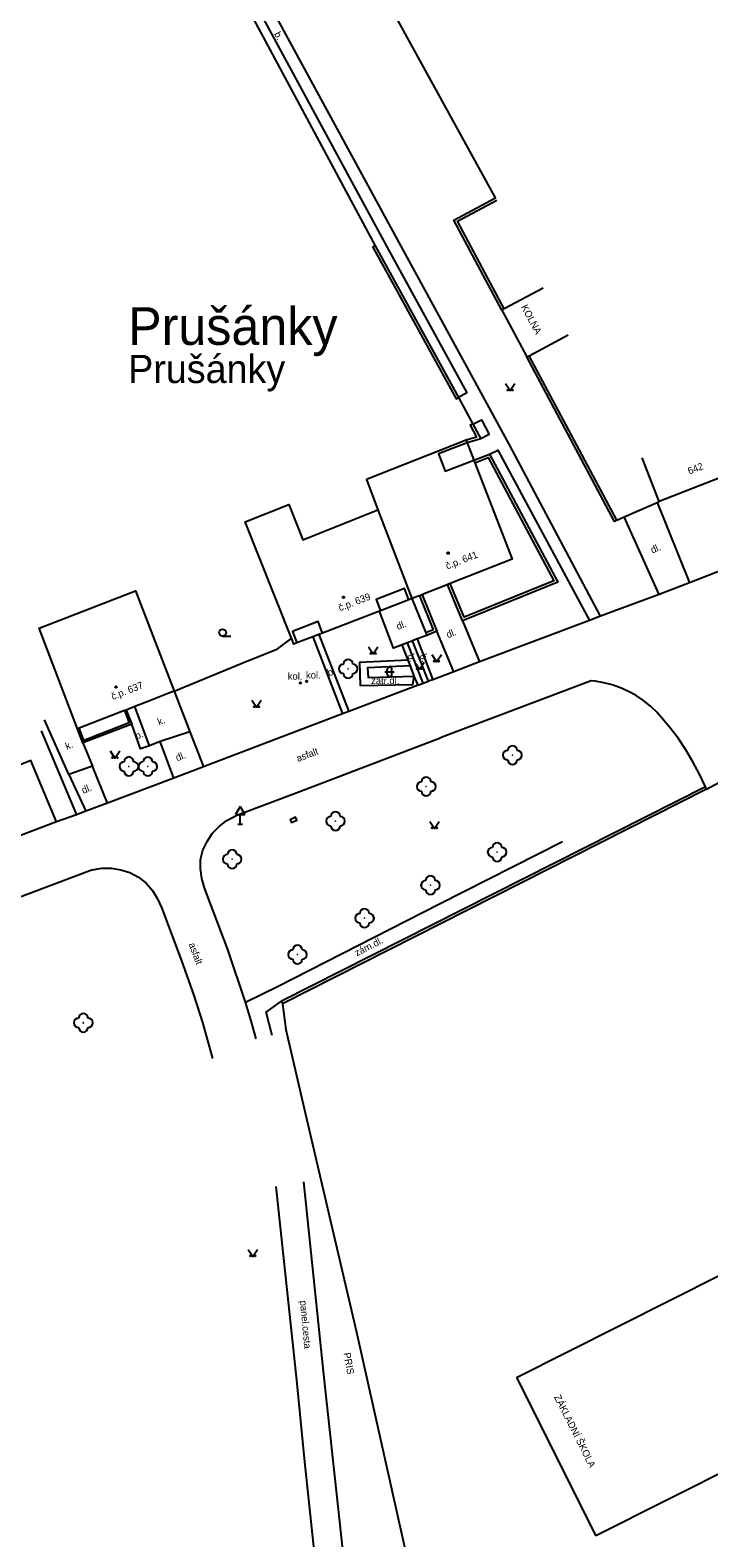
# Model space of a CAD drawing. Extents: x -577457 to -568404, y -1208466 to -1201387.
# Drawn here: x -574973.4 to -574901.1, y -1204276 to -1204115.5 of the extents above; entities that cross this region are included whole.
import ezdxf

# ---------------------------------------------------------------- set-up
doc = ezdxf.new("R2010")
doc.units = 0
for name, color, linetype in [('BUDOVY_MĚŘ', 7, 'Continuous'), ('BUDOVY_NEMĚŘ', 7, 'Continuous'), ('NÁZEV_K_Ú', 7, 'Continuous'), ('NÁZVY_SÍDEL_JEDNOTKY', 7, 'Continuous'), ('OBVOD_PILÍŘE', 7, 'Continuous'), ('POMOC_POPIS', 7, 'Continuous'), ('ROZHRANÍ_PLOCH', 7, 'Continuous'), ('ZELEŇ', 7, 'Continuous'), ('ZN_BP', 7, 'Continuous'), ('ZN_BUDOV', 7, 'Continuous'), ('ZN_DOPLŇKOVÉ', 7, 'Continuous'), ('ZN_KULTUR', 7, 'Continuous'), ('Č_POPIS_ORIENT', 7, 'Continuous')]:
    doc.layers.add(name, color=color, linetype=linetype)

msp = doc.modelspace()

# ---------------------------------------------------------------- linework, layer by layer
at = {"layer": 'BUDOVY_MĚŘ'}
for points in [[(-574918.74, -1204143), (-574922.89, -1204145.21)], [(-574922.89, -1204145.21), (-574923.15, -1204145.35)], [(-574923.15, -1204145.35), (-574920.5, -1204150.32)], [(-574920.23, -1204150.18), (-574916.09, -1204147.96)], [(-574920.5, -1204150.32), (-574920.23, -1204150.18)], [(-574926.96, -1204159.17), (-574926.85, -1204159.45)], [(-574926.85, -1204159.45), (-574926.14, -1204161.3)], [(-574926.03, -1204161.58), (-574922.06, -1204171.84), (-574928.65, -1204174.43)], [(-574926.14, -1204161.3), (-574926.03, -1204161.58)], [(-574906.38, -1204165.7), (-574908.2, -1204161.05)], [(-574897.04, -1204162.05), (-574906.38, -1204165.7)], [(-574928.93, -1204174.54), (-574928.98, -1204174.56)], [(-574928.65, -1204174.43), (-574928.93, -1204174.54)], [(-574933.04, -1204176.15), (-574933.5, -1204174.96), (-574936.52, -1204176.12), (-574936.06, -1204177.32)], [(-574933.04, -1204176.15), (-574936.06, -1204177.32)], [(-574932.72, -1204176.03), (-574933.04, -1204176.15)], [(-574931.91, -1204175.72), (-574932.72, -1204176.03)], [(-574931.64, -1204175.61), (-574931.91, -1204175.72)], [(-574931.58, -1204175.59), (-574931.64, -1204175.61)], [(-574936.17, -1204177.36), (-574942.23, -1204179.7)], [(-574936.06, -1204177.32), (-574936.17, -1204177.36)], [(-574942.23, -1204179.7), (-574942.69, -1204178.48), (-574945.45, -1204179.54), (-574944.99, -1204180.75)], [(-574944.99, -1204180.75), (-574945.29, -1204180.87), (-574945.54, -1204180.22)], [(-574943.29, -1204180.1), (-574944.99, -1204180.75)], [(-574942.63, -1204179.85), (-574943.29, -1204180.1)], [(-574942.23, -1204179.7), (-574942.63, -1204179.85)], [(-574960.91, -1204187.01), (-574962.22, -1204187.52)], [(-574958.04, -1204185.88), (-574958.6, -1204186.1)], [(-574963.34, -1204187.95), (-574968.15, -1204189.83)], [(-574963.15, -1204187.88), (-574963.34, -1204187.95)], [(-574968.15, -1204189.83), (-574968.34, -1204189.9)], [(-574921.6, -1204258.9), (-574913.15, -1204275.74)]]:
    msp.add_lwpolyline(points, dxfattribs=at)
at = {"layer": 'BUDOVY_NEMĚŘ'}
for points in [[(-574926.96, -1204159.17), (-574937.56, -1204163.35), (-574936.34, -1204166.57)], [(-574945.54, -1204180.22), (-574950.47, -1204167.87), (-574945.82, -1204166.03), (-574944.34, -1204169.79), (-574936.34, -1204166.57)], [(-574936.34, -1204166.57), (-574932.72, -1204176.03)], [(-574968.34, -1204189.9), (-574972.43, -1204179.19), (-574962.16, -1204175.19), (-574958.04, -1204185.88)], [(-574857.68, -1204191.68), (-574846.58, -1204213.64), (-574853.89, -1204217.28), (-574849.2, -1204226.67), (-574843.69, -1204223.72), (-574821.59, -1204212.63), (-574815.65, -1204224.53), (-574833.36, -1204233.58), (-574843.21, -1204238.37), (-574841.8, -1204241.19), (-574860.48, -1204250.63), (-574874.45, -1204257.68), (-574874.99, -1204256.6), (-574913.15, -1204275.74)], [(-574921.6, -1204258.9), (-574883.43, -1204239.7), (-574880.79, -1204244.93), (-574850.83, -1204229.95), (-574856.48, -1204218.65), (-574863.63, -1204222.13), (-574874.59, -1204200.08)]]:
    msp.add_lwpolyline(points, dxfattribs=at)
at = {"layer": 'OBVOD_PILÍŘE'}
msp.add_lwpolyline([(-574945.39, -1204199.42), (-574945.67, -1204199.55), (-574945.54, -1204199.84), (-574944.98, -1204199.59), (-574945.11, -1204199.3), (-574945.39, -1204199.42)], dxfattribs=at)
at = {"layer": 'ROZHRANÍ_PLOCH'}
for points in [[(-574912.63, -1204177.88), (-574922.36, -1204159.6), (-574934.08, -1204138.15), (-574950.93, -1204107.14), (-574981.16, -1204051.23), (-574986.68, -1204040.91), (-574973.68, -1204036.43), (-574971.26, -1204041.76)], [(-574996.39, -1204050.09), (-574998.78, -1204045.04), (-574987.93, -1204041.41), (-574982.39, -1204051.92), (-574952.04, -1204107.85), (-574935.21, -1204138.91), (-574926.87, -1204154.13), (-574927.75, -1204154.64)], [(-574926.25, -1204157.45), (-574925.32, -1204156.99), (-574924.49, -1204158.55), (-574925.38, -1204159.03)], [(-574924.46, -1204160.65), (-574923.59, -1204160.25), (-574913.81, -1204178.36)], [(-574906.61, -1204165.8), (-574903.18, -1204174.35)], [(-574906.38, -1204175.59), (-574910.11, -1204167.33)], [(-574892.87, -1204170.33), (-574903.18, -1204174.35)], [(-574903.18, -1204174.35), (-574906.38, -1204175.59)], [(-574932.72, -1204176.03), (-574931.25, -1204179.68)], [(-574906.38, -1204175.59), (-574912.63, -1204177.88)], [(-574933.77, -1204180.95), (-574934.7, -1204181.29), (-574936.17, -1204177.36)], [(-574927.32, -1204178.38), (-574925.51, -1204182.76)], [(-574913.81, -1204178.36), (-574925.51, -1204182.76)], [(-574912.63, -1204177.88), (-574913.81, -1204178.36)], [(-574943.29, -1204180.1), (-574940.11, -1204188.29)], [(-574942.63, -1204179.85), (-574939.45, -1204188.04)], [(-574933.2, -1204180.72), (-574933.77, -1204180.95)], [(-574933.13, -1204182.58), (-574933.77, -1204180.95)], [(-574932.66, -1204180.52), (-574933.2, -1204180.72)], [(-574931.53, -1204185.04), (-574933.2, -1204180.72)], [(-574932.18, -1204180.32), (-574932.66, -1204180.52)], [(-574930.97, -1204184.81), (-574932.66, -1204180.52)], [(-574931.14, -1204179.96), (-574932.18, -1204180.32)], [(-574932.18, -1204180.32), (-574930.5, -1204184.66)], [(-574931.25, -1204179.68), (-574931.14, -1204179.96)], [(-574928.27, -1204183.82), (-574930.07, -1204179.5)], [(-574933.13, -1204182.58), (-574938.29, -1204182.84), (-574938.24, -1204185.26), (-574932.63, -1204185.18), (-574932.47, -1204184.27)], [(-574932.89, -1204183.17), (-574933.13, -1204182.58)], [(-574932.89, -1204183.17), (-574937.45, -1204183.41), (-574937.39, -1204184.41), (-574932.47, -1204184.27)], [(-574932.47, -1204184.27), (-574932.89, -1204183.17)], [(-574928.27, -1204183.82), (-574930.5, -1204184.66)], [(-574925.51, -1204182.76), (-574928.27, -1204183.82)], [(-574932.06, -1204185.24), (-574939.45, -1204188.04)], [(-574932.06, -1204185.24), (-574932.47, -1204184.27)], [(-574932.06, -1204185.24), (-574931.53, -1204185.04)], [(-574931.53, -1204185.04), (-574930.97, -1204184.81)], [(-574930.5, -1204184.66), (-574930.97, -1204184.81)], [(-574901.48, -1204196.05), (-574902.1, -1204194.7), (-574902.8, -1204193.39), (-574903.56, -1204192.12), (-574904.39, -1204190.89), (-574905.29, -1204189.71), (-574906.04, -1204188.81), (-574906.66, -1204188.11), (-574907.33, -1204187.46), (-574908.06, -1204186.88), (-574908.84, -1204186.35), (-574909.65, -1204185.9), (-574910.51, -1204185.52), (-574911.39, -1204185.21), (-574912.3, -1204184.98), (-574913.22, -1204184.82), (-574913.65, -1204184.78), (-574929.62, -1204190.82)], [(-574958.04, -1204185.88), (-574956.38, -1204190.22)], [(-574969.27, -1204194.73), (-574971.83, -1204188.93)], [(-574960.67, -1204191.68), (-574962.22, -1204187.52)], [(-574940.11, -1204188.29), (-574954.92, -1204193.91)], [(-574939.45, -1204188.04), (-574940.11, -1204188.29)], [(-574972.19, -1204190.11), (-574968.44, -1204199.03)], [(-574960.67, -1204191.68), (-574961.61, -1204192.02), (-574962.56, -1204189.37)], [(-574956.38, -1204190.22), (-574959.53, -1204191.24)], [(-574956.38, -1204190.22), (-574954.92, -1204193.91)], [(-574967.77, -1204191.39), (-574966.74, -1204193.85)], [(-574959.53, -1204191.24), (-574960.67, -1204191.68)], [(-574958.08, -1204195.13), (-574959.53, -1204191.24)], [(-574950.46, -1204218.96), (-574952.33, -1204213.35), (-574954.44, -1204207.77), (-574954.81, -1204206.81), (-574955.09, -1204205.82), (-574955.25, -1204204.79), (-574955.24, -1204203.79), (-574954.98, -1204202.79), (-574954.52, -1204201.88), (-574953.99, -1204201.02), (-574953.25, -1204200.28), (-574952.43, -1204199.64), (-574951.37, -1204199.06), (-574944.77, -1204196.57), (-574929.62, -1204190.82)], [(-574970.56, -1204199.78), (-574973.31, -1204193.25), (-574975.69, -1204194.2), (-574975.77, -1204193.97)], [(-574966.74, -1204193.85), (-574969.27, -1204194.73)], [(-574969.27, -1204194.73), (-574967.44, -1204198.65)], [(-574965.14, -1204197.78), (-574966.74, -1204193.85)], [(-574958.08, -1204195.13), (-574965.14, -1204197.78)], [(-574954.92, -1204193.91), (-574958.08, -1204195.13)], [(-574965.14, -1204197.78), (-574967.44, -1204198.65)], [(-574970.56, -1204199.78), (-574990.65, -1204207.4)], [(-574968.44, -1204199.03), (-574970.56, -1204199.78)], [(-574967.44, -1204198.65), (-574968.44, -1204199.03)], [(-574950.46, -1204218.96), (-574947.05, -1204217.3), (-574929.78, -1204208.52), (-574916.7, -1204201.87)], [(-574966.75, -1204204.9), (-574992.17, -1204214.47), (-574994.4, -1204215.31)], [(-574966.75, -1204204.9), (-574965.75, -1204204.7), (-574964.73, -1204204.7), (-574963.71, -1204204.88), (-574962.77, -1204205.18), (-574961.85, -1204205.66), (-574961.02, -1204206.3), (-574960.34, -1204207.08), (-574959.81, -1204207.98), (-574959.4, -1204208.9), (-574957.28, -1204214.48), (-574955.93, -1204218.26), (-574955.02, -1204221.14), (-574953.94, -1204224.95)], [(-574949.31, -1204222.86), (-574949.83, -1204220.94), (-574950.46, -1204218.96)], [(-574947.59, -1204222.5), (-574948.26, -1204220.02), (-574946.62, -1204218.87)], [(-574939.08, -1204315.07), (-574939.86, -1204308.3), (-574940.56, -1204301.52), (-574941.18, -1204294.73), (-574941.48, -1204290.96), (-574942.19, -1204285.23), (-574943.19, -1204276.55), (-574944.12, -1204267.87), (-574944.96, -1204259.17), (-574947.18, -1204238.57)], [(-574939.55, -1204282.09), (-574942.11, -1204258.6), (-574944.24, -1204238.07)]]:
    msp.add_lwpolyline(points, dxfattribs=at)
at = {"layer": 'ZELEŇ'}
for centre in [(-574939.5, -1204183.5), (-574922.03, -1204192.68), (-574962.85, -1204193.88), (-574960.85, -1204193.9), (-574931.19, -1204196.02), (-574940.86, -1204199.7), (-574923.66, -1204203), (-574951.87, -1204203.76), (-574930.76, -1204206.52), (-574937.76, -1204210.03), (-574944.9, -1204213.9), (-574967.71, -1204221.16)]:
    msp.add_circle(centre, 0.0005, dxfattribs=at)
for centre, start, end in [((-574939.5, -1204183), 0, 180), ((-574940, -1204183.5), 90, 270), ((-574939.5, -1204184), 180, 360), ((-574939, -1204183.5), 270, 90), ((-574922.53, -1204192.68), 90, 270), ((-574922.03, -1204192.18), 0, 180), ((-574921.53, -1204192.68), 270, 90), ((-574963.35, -1204193.88), 90, 270), ((-574962.85, -1204193.38), 0, 180), ((-574962.35, -1204193.88), 270, 90), ((-574961.35, -1204193.9), 90, 270), ((-574960.85, -1204193.4), 0, 180), ((-574960.35, -1204193.9), 270, 90), ((-574922.03, -1204193.18), 180, 360), ((-574962.85, -1204194.38), 180, 360), ((-574960.85, -1204194.4), 180, 360), ((-574931.19, -1204195.52), 0, 180), ((-574931.69, -1204196.02), 90, 270), ((-574931.19, -1204196.52), 180, 360), ((-574930.69, -1204196.02), 270, 90), ((-574941.36, -1204199.7), 90, 270), ((-574940.86, -1204199.2), 0, 180), ((-574940.86, -1204200.2), 180, 360), ((-574940.36, -1204199.7), 270, 90), ((-574952.37, -1204203.76), 90, 270), ((-574951.87, -1204203.26), 0, 180), ((-574951.37, -1204203.76), 270, 90), ((-574924.16, -1204203), 90, 270), ((-574923.66, -1204202.5), 0, 180), ((-574923.16, -1204203), 270, 90), ((-574951.87, -1204204.26), 180, 360), ((-574923.66, -1204203.5), 180, 360), ((-574931.26, -1204206.52), 90, 270), ((-574930.76, -1204206.02), 0, 180), ((-574930.26, -1204206.52), 270, 90), ((-574930.76, -1204207.02), 180, 360), ((-574938.26, -1204210.03), 90, 270), ((-574937.76, -1204209.53), 0, 180), ((-574937.26, -1204210.03), 270, 90), ((-574937.76, -1204210.53), 180, 360), ((-574944.9, -1204213.4), 0, 180), ((-574945.4, -1204213.9), 90, 270), ((-574944.9, -1204214.4), 180, 360), ((-574944.4, -1204213.9), 270, 90), ((-574968.21, -1204221.16), 90, 270), ((-574967.71, -1204220.66), 0, 180), ((-574967.21, -1204221.16), 270, 90), ((-574967.71, -1204221.66), 180, 360)]:
    msp.add_arc(centre, 0.5, start, end, dxfattribs=at)
at = {"layer": 'ZN_BP'}
for centre in [(-574944.6, -1204184.99), (-574943.94, -1204184.83)]:
    msp.add_circle(centre, 0.075, dxfattribs=at)
at = {"layer": 'ZN_BUDOV'}
for centre in [(-574928.87, -1204171.19), (-574940.01, -1204175.9), (-574964.24, -1204185.43)]:
    msp.add_circle(centre, 0.0875, dxfattribs=at)
at = {"layer": 'ZN_DOPLŇKOVÉ'}
for p, q in [((-574951.01, -1204198.14), (-574951.51, -1204199.01)), ((-574951.01, -1204198.14), (-574950.51, -1204199.01)), ((-574951.51, -1204199.01), (-574950.51, -1204199.01)), ((-574951.26, -1204200.01), (-574950.76, -1204200.01)), ((-574951.01, -1204200.01), (-574951.01, -1204199.01))]:
    msp.add_line(p, q, dxfattribs=at)
for points in [[(-574923.15, -1204145.35), (-574928.27, -1204135.75), (-574923.82, -1204133.38), (-574961.09, -1204065.62)], [(-574952.76, -1204108.45), (-574936.63, -1204138.5)], [(-574922.89, -1204145.21), (-574927.87, -1204135.87), (-574923.68, -1204133.64)], [(-574936.63, -1204138.5), (-574936.9, -1204138.64), (-574928.01, -1204154.78), (-574927.75, -1204154.64)], [(-574936.63, -1204138.5), (-574927.75, -1204154.64)], [(-574910.91, -1204167.68), (-574911.17, -1204167.82), (-574920.5, -1204150.32)], [(-574910.91, -1204167.68), (-574920.23, -1204150.18)], [(-574927.75, -1204154.64), (-574926.25, -1204157.45)], [(-574926.25, -1204157.45), (-574926.51, -1204157.59), (-574925.83, -1204158.84), (-574926.96, -1204159.17)], [(-574926.25, -1204157.45), (-574925.38, -1204159.03)], [(-574926.85, -1204159.45), (-574929.88, -1204160.62), (-574929.17, -1204162.47), (-574926.14, -1204161.3)], [(-574925.38, -1204159.03), (-574926.85, -1204159.45)], [(-574926.03, -1204161.58), (-574924.6, -1204161.02), (-574917.62, -1204174.14), (-574927.16, -1204177.99), (-574928.65, -1204174.43)], [(-574924.46, -1204160.65), (-574917.2, -1204174.29), (-574927.32, -1204178.38)], [(-574926.14, -1204161.3), (-574924.46, -1204160.65)], [(-574910.11, -1204167.33), (-574906.61, -1204165.8)], [(-574906.61, -1204165.8), (-574906.38, -1204165.7)], [(-574910.91, -1204167.68), (-574910.11, -1204167.33)], [(-574928.98, -1204174.56), (-574931.58, -1204175.59)], [(-574927.32, -1204178.38), (-574928.93, -1204174.54)], [(-574931.91, -1204175.72), (-574930.46, -1204179.34), (-574931.25, -1204179.68)], [(-574931.64, -1204175.61), (-574930.07, -1204179.5)], [(-574945.54, -1204180.22), (-574947.12, -1204181.41)], [(-574930.07, -1204179.5), (-574931.14, -1204179.96)], [(-574950.92, -1204182.92), (-574947.12, -1204181.41)], [(-574958.04, -1204185.88), (-574950.92, -1204182.92)], [(-574958.6, -1204186.1), (-574960.91, -1204187.01)], [(-574963.34, -1204187.95), (-574962.82, -1204189.26), (-574967.66, -1204191.13), (-574968.15, -1204189.83)], [(-574962.22, -1204187.52), (-574963.15, -1204187.88)], [(-574963.15, -1204187.88), (-574962.56, -1204189.37)], [(-574967.77, -1204191.39), (-574968.34, -1204189.9)], [(-574962.56, -1204189.37), (-574967.77, -1204191.39)], [(-574901.35, -1204196.32), (-574898.6, -1204194.82)], [(-574901.48, -1204196.05), (-574946.62, -1204218.87), (-574946.49, -1204219.14)], [(-574901.35, -1204196.32), (-574946.49, -1204219.14)], [(-574901.35, -1204196.32), (-574901.48, -1204196.05)], [(-574946.49, -1204219.14), (-574946.14, -1204221.86)], [(-574946.14, -1204221.86), (-574944.09, -1204230.75), (-574938.64, -1204254.09), (-574931.86, -1204284.35)]]:
    msp.add_lwpolyline(points, dxfattribs=at)
at = {"layer": 'ZN_KULTUR'}
for p, q in [((-574952.88, -1204180.03), (-574952.01, -1204180.03)), ((-574935.6, -1204183.81), (-574934.6, -1204183.81)), ((-574935.35, -1204184.06), (-574935.35, -1204183.56)), ((-574934.85, -1204184.06), (-574934.85, -1204183.56))]:
    msp.add_line(p, q, dxfattribs=at)
for points in [[(-574922.75, -1204153.15), (-574922.25, -1204153.9), (-574921.75, -1204153.15)], [(-574937.34, -1204181.16), (-574936.84, -1204181.91), (-574936.34, -1204181.16)], [(-574930.59, -1204181.99), (-574930.09, -1204182.74), (-574929.59, -1204181.99)], [(-574932.41, -1204182.8), (-574931.91, -1204183.55), (-574931.41, -1204182.8)], [(-574949.77, -1204186.84), (-574949.27, -1204187.59), (-574948.77, -1204186.84)], [(-574964.84, -1204192.24), (-574964.34, -1204192.99), (-574963.84, -1204192.24)], [(-574930.83, -1204199.73), (-574930.33, -1204200.48), (-574929.83, -1204199.73)], [(-574950.15, -1204245.27), (-574949.65, -1204246.02), (-574949.15, -1204245.27)]]:
    msp.add_lwpolyline(points, dxfattribs=at)
for centre, radius in [((-574922.5, -1204153.85), 0.05), ((-574922, -1204153.85), 0.05), ((-574952.88, -1204179.66), 0.375), ((-574937.09, -1204181.86), 0.05), ((-574936.59, -1204181.86), 0.05), ((-574932.16, -1204183.5), 0.05), ((-574931.66, -1204183.5), 0.05), ((-574930.34, -1204182.69), 0.05), ((-574929.84, -1204182.69), 0.05), ((-574949.52, -1204187.54), 0.05), ((-574949.02, -1204187.54), 0.05), ((-574964.59, -1204192.94), 0.05), ((-574964.09, -1204192.94), 0.05), ((-574930.58, -1204200.43), 0.05), ((-574930.08, -1204200.43), 0.05), ((-574949.9, -1204245.97), 0.05), ((-574949.4, -1204245.97), 0.05)]:
    msp.add_circle(centre, radius, dxfattribs=at)
for centre, start, end in [((-574935.1, -1204183.56), 0, 180), ((-574935.1, -1204184.06), 180, 360)]:
    msp.add_arc(centre, 0.25, start, end, dxfattribs=at)

# ---------------------------------------------------------------- texts
at = {"layer": 'NÁZEV_K_Ú'}
msp.add_text('Prušánky', height=3, dxfattribs=at).set_placement((-574962.94, -1204153.09))
at = {"layer": 'NÁZVY_SÍDEL_JEDNOTKY'}
msp.add_text('Prušánky', height=4, dxfattribs=at).set_placement((-574962.94, -1204149.03))
at = {"layer": 'POMOC_POPIS'}
for s, rotation, p in [('b.', 298.52, (-574947.43, -1204115.95)), ('KOLNA', 298.13, (-574921.13, -1204144.99)), ('dl.', 23.53, (-574907.11, -1204171.25)), ('dl.', 21.06, (-574934.22, -1204179.38)), ('dl.', 21.06, (-574928.9, -1204180.25)), ('b.', 291.4369, (-574933.22, -1204182.07)), ('b.', 291.5014, (-574931.91, -1204182.07)), ('b.', 21.06, (-574941.56, -1204184.31)), ('k.', 21.29, (-574959.64, -1204189.53)), ('b.', 21.29, (-574962.02, -1204191.02)), ('k.', 21.29, (-574969.46, -1204192.11)), ('asfalt', 20.7836, (-574944.86, -1204193.42)), ('dl.', 21.29, (-574957.71, -1204193.35)), ('dl.', 21.29, (-574967.72, -1204196.81)), ('asfalt', 290.8032, (-574956.52, -1204212.8)), ('zám.dl.', 26.9486, (-574938.59, -1204214.1)), ('panel.cesta', 275.32, (-574944.65, -1204250.75)), ('PRIS', 280.65, (-574940.02, -1204256.32)), ('ZÁKLADNÍ ŠKOLA', 296.65, (-574917.61, -1204260.97))]:
    msp.add_text(s, height=0.75, rotation=rotation, dxfattribs=at).set_placement(p)
for s, p in [('kol.', (-574945.94, -1204184.65)), ('kol.', (-574944, -1204184.53)), ('zatr.dl.', (-574937.07, -1204185.12))]:
    msp.add_text(s, height=0.75, dxfattribs=at).set_placement(p)
at = {"layer": 'Č_POPIS_ORIENT'}
for s, rotation, p in [('642', 21.37, (-574903.18, -1204162.84)), ('č.p. 641', 21.46, (-574928.96, -1204172.94)), ('č.p. 639', 21.06, (-574940.38, -1204177.38)), ('č.p. 637', 21.29, (-574964.58, -1204186.82))]:
    msp.add_text(s, height=0.75, rotation=rotation, dxfattribs=at).set_placement(p)

doc.saveas('drawing.dxf')
